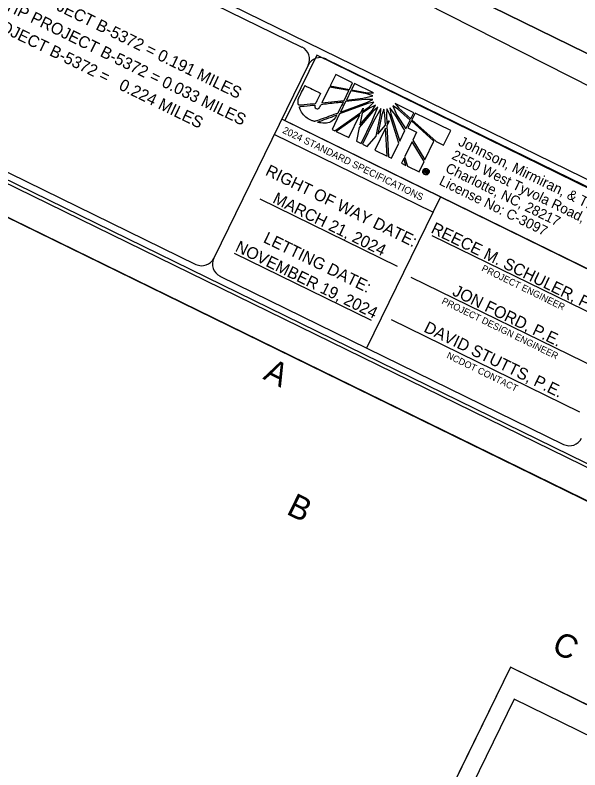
# Model space of a CAD drawing. Extents: x 1517888 to 1526099, y 633375 to 640181.
# Drawn here: x 1519355 to 1520197, y 636669 to 637793 of the extents above; entities that cross this region are included whole.
import ezdxf

# ---------------------------------------------------------------- set-up
doc = ezdxf.new("R2010")
doc.units = 0
for name, color, linetype in [('Scratch_Level_0', 7, 'Continuous'), ('Sheet Clip Boundary CELL', 7, 'Continuous'), ('Sheet Cutting Line CELL', 7, 'Continuous'), ('Sheet Data Field CELL', 7, 'Continuous'), ('Sheet Data Text CELL', 7, 'Continuous'), ('Sheet Plot Border Inside CELL', 7, 'Continuous'), ('Sheet Plot Border Outside CELL', 7, 'Continuous'), ('Sheet Title CELL', 7, 'Continuous')]:
    doc.layers.add(name, color=color, linetype=linetype)

msp = doc.modelspace()

# ---------------------------------------------------------------- linework, layer by layer
at = {"layer": 'Scratch_Level_0'}
msp.add_lwpolyline([(1519830.7, 639089.6), (1521178.1, 638430.5), (1520716.8, 637487.3), (1519369.3, 638146.3)], close=True, dxfattribs=at)
at = {"layer": 'Sheet Clip Boundary CELL'}
msp.add_lwpolyline([(1519997.2, 638878.2), (1520677.9, 638519.7), (1521000.4, 638385.3), (1521102.7, 638308.6), (1521171, 638278.9), (1521396, 638166), (1521492.2, 638121.5), (1521760.4, 637993.1), (1521455.7, 637316.3), (1521359.7, 637143.3), (1520290, 637647.3), (1519534.4, 638030.1)], close=True, dxfattribs=at)
at = {"layer": 'Sheet Cutting Line CELL'}
for p, q in [((1518399.9, 637954.2), (1521425.5, 636474.5)), ((1520093.5, 636822.1), (1519131.3, 634854.8)), ((1523118.1, 635342.8), (1520093.5, 636822.1))]:
    msp.add_line(p, q, dxfattribs=at)
at = {"layer": 'Sheet Plot Border Inside CELL'}
for points in [[(1517931.1, 638233.4), (1520925.2, 636769.1), (1521852.3, 638664.7), (1518858.2, 640129.1)], [(1519172.2, 634879.3), (1522165.4, 633415.4), (1523092.5, 635310.8), (1520099.3, 636774.7)]]:
    msp.add_lwpolyline(points, close=True, dxfattribs=at)
at = {"layer": 'Sheet Plot Border Outside CELL'}
for points in [[(1521880.1, 638701.1), (1518854.6, 640180.8), (1517888, 638204.5), (1520913.6, 636724.8)], [(1519131.3, 634854.8), (1522155.9, 633375.5), (1523118.1, 635342.8), (1520093.5, 636822.1)]]:
    msp.add_lwpolyline(points, close=True, dxfattribs=at)
at = {"layer": 'Sheet Title CELL'}
for p, q in [((1518493.8, 638387), (1521045, 637139.2)), ((1519100.2, 638079.2), (1519782.9, 637745.3)), ((1519818.9, 637727.7), (1520330.9, 637477.3)), ((1519792.1, 637718.6), (1519651.5, 637431.1)), ((1519833.1, 637704.6), (1519824.9, 637687.9)), ((1519858.3, 637692.3), (1519833.1, 637704.6)), ((1519824.9, 637687.9), (1519853.6, 637682.6)), ((1519853.6, 637682.6), (1519858.3, 637692.3)), ((1519861, 637691.2), (1519856.6, 637682.1)), ((1519889.4, 637677.3), (1519861, 637691.2)), ((1519824, 637686), (1519812.5, 637662.5)), ((1519852.7, 637680.7), (1519824, 637686)), ((1519845.6, 637666.1), (1519852.7, 637680.7)), ((1519855.7, 637680.2), (1519849, 637666.5)), ((1519879.7, 637675.7), (1519855.7, 637680.2)), ((1519856.6, 637682.1), (1519880.6, 637677.6)), ((1519880.6, 637677.6), (1519889.4, 637677.3)), ((1519812.5, 637662.5), (1519845.6, 637666.1)), ((1519876.6, 637667.6), (1519847.9, 637664.3)), ((1519849, 637666.5), (1519873.8, 637669.3)), ((1519873.8, 637669.3), (1519888.4, 637672.7)), ((1519888.6, 637667.7), (1519876.6, 637667.6)), ((1519888.4, 637672.7), (1519879.7, 637675.7)), ((1519880.4, 637663.3), (1519888.6, 637667.7)), ((1519880.8, 637661.4), (1519838.9, 637645.9)), ((1519847.9, 637664.3), (1519840.2, 637648.6)), ((1519840.2, 637648.6), (1519880.4, 637663.3)), ((1519870.7, 637648.2), (1519874, 637654.8)), ((1519884.4, 637655.3), (1519872.5, 637646.9)), ((1519873, 637649.6), (1519883, 637656.7)), ((1519874, 637654.8), (1519873, 637649.6)), ((1519890, 637663.3), (1519880.8, 637661.4)), ((1519883, 637656.7), (1519890, 637663.3)), ((1519892.5, 637659.2), (1519884.4, 637655.3)), ((1519887.5, 637635.7), (1519896.1, 637656.1)), ((1519888, 637651.8), (1519892.5, 637659.2)), ((1519896.1, 637656.1), (1519888.7, 637649.7)), ((1519914, 637655.3), (1519915.5, 637646)), ((1519921.4, 637645.7), (1519914, 637655.3)), ((1519918.1, 637658.2), (1519924.5, 637644.3)), ((1519925.4, 637653.4), (1519918.1, 637658.2)), ((1519949.5, 637647.8), (1519921.6, 637661.6)), ((1519921.6, 637661.6), (1519927, 637654.8)), ((1519927, 637654.8), (1519945.1, 637638.8)), ((1519838.9, 637645.9), (1519827.8, 637623)), ((1519831.9, 637621), (1519870.7, 637648.2)), ((1519869, 637644.6), (1519833.9, 637620)), ((1519852.7, 637610.8), (1519869, 637644.6)), ((1519888.7, 637649.7), (1519868.3, 637625.9)), ((1519869.2, 637629.8), (1519888, 637651.8)), ((1519872.5, 637646.9), (1519869.2, 637629.8)), ((1519900.3, 637654.1), (1519889.3, 637634.8)), ((1519893.4, 637613.1), (1519899.7, 637644.4)), ((1519901.8, 637644.7), (1519895.9, 637616)), ((1519899.7, 637644.4), (1519900.3, 637654.1)), ((1519904.9, 637653.2), (1519901.8, 637644.7)), ((1519906.6, 637644.4), (1519904.9, 637653.2)), ((1519907.4, 637629.4), (1519906.6, 637644.4)), ((1519909.6, 637653.7), (1519908.7, 637644.1)), ((1519908.7, 637644.1), (1519909.2, 637631.5)), ((1519913.8, 637645.3), (1519909.6, 637653.7)), ((1519927.2, 637602.5), (1519913.8, 637645.3)), ((1519915.5, 637646), (1519928.5, 637605.2)), ((1519936.4, 637621.3), (1519921.4, 637645.7)), ((1519924.5, 637644.3), (1519937.5, 637623.6)), ((1519944.1, 637636.8), (1519925.4, 637653.4)), ((1519945.1, 637638.8), (1519949.5, 637647.8)), ((1519951.5, 637647), (1519946.8, 637637.3)), ((1520004.6, 637621.1), (1519951.5, 637647)), ((1520300.8, 637370.1), (1519752.8, 637638.2)), ((1519871.1, 637602), (1519887.5, 637635.7)), ((1519889.3, 637634.8), (1519872.9, 637601.1)), ((1519909.2, 637631.5), (1519913, 637635.8)), ((1519913, 637635.8), (1519909.4, 637628.4)), ((1519937.5, 637623.6), (1519944.1, 637636.8)), ((1519945.8, 637635.3), (1519940.9, 637625.1)), ((1519945.9, 637635.5), (1519945.8, 637635.3)), ((1519979.6, 637605.2), (1519945.9, 637635.5)), ((1519946.8, 637637.3), (1519946.6, 637637)), ((1519946.6, 637637), (1519982.7, 637604.9)), ((1519827.8, 637623), (1519831.9, 637621)), ((1519868.3, 637625.9), (1519864.2, 637605.4)), ((1519907.6, 637624.8), (1519891.6, 637592)), ((1519895.9, 637616), (1519907.4, 637629.4)), ((1519909.7, 637583.2), (1519907.6, 637624.8)), ((1519909.4, 637628.4), (1519911.7, 637582)), ((1519928.5, 637605.2), (1519936.4, 637621.3)), ((1519940.9, 637625.1), (1519953.8, 637618.8)), ((1519994, 637599.4), (1520004.6, 637621.1)), ((1519977.9, 637499.6), (1519741.6, 637615.3)), ((1519833.9, 637620), (1519852.7, 637610.8)), ((1519879.9, 637597.7), (1519893.4, 637613.1)), ((1519953.8, 637618.8), (1519947.9, 637606.7)), ((1519864.2, 637605.4), (1519871.1, 637602)), ((1519872.9, 637601.1), (1519879.9, 637597.7)), ((1519916.1, 637579.9), (1519927.2, 637602.5)), ((1519946.9, 637604.6), (1519935.9, 637582.1)), ((1519965, 637575.4), (1519946.9, 637604.6)), ((1519947.9, 637606.7), (1519966, 637577.4)), ((1519966, 637577.4), (1519979.6, 637605.2)), ((1519982.7, 637604.9), (1519994, 637599.4)), ((1519891.6, 637592), (1519909.7, 637583.2)), ((1519911.7, 637582), (1519916.1, 637579.9)), ((1519934.7, 637579.6), (1519931.2, 637572.5)), ((1519937.8, 637569.3), (1519934.7, 637579.6)), ((1519935.9, 637582.1), (1519940.3, 637568.1)), ((1519931.2, 637572.5), (1519937.8, 637569.3)), ((1519940.3, 637568.1), (1519957.4, 637559.8)), ((1519957.4, 637559.8), (1519965, 637575.4)), ((1519969.8, 637564.3), (1519969.4, 637563.5)), ((1519969.4, 637563.5), (1519969.8, 637564.3)), ((1519965.2, 637558.9), (1519967.1, 637562.8)), ((1519966.1, 637558.5), (1519965.2, 637558.9)), ((1519966, 637556.6), (1519965.6, 637555.8)), ((1519965.6, 637555.8), (1519966, 637556.6)), ((1519965.7, 637555.8), (1519965.6, 637555.8)), ((1519966, 637556.6), (1519966.1, 637556.6)), ((1519966.8, 637560), (1519966.1, 637558.5)), ((1519967.5, 637559.6), (1519966.8, 637560)), ((1519967.1, 637562.8), (1519968.6, 637562)), ((1519967.6, 637561.6), (1519967.1, 637560.7)), ((1519967.1, 637560.7), (1519967.8, 637560.3)), ((1519967.8, 637560.3), (1519967.5, 637559.6)), ((1519967.5, 637559.6), (1519967.8, 637560.3)), ((1519967.5, 637559.6), (1519967.5, 637559.6)), ((1519968.3, 637561.2), (1519967.6, 637561.6)), ((1519967.8, 637560.3), (1519967.9, 637560.3)), ((1519968.6, 637562), (1519968.3, 637561.2)), ((1519968.3, 637561.2), (1519968.6, 637562)), ((1519968.4, 637561.2), (1519968.3, 637561.2)), ((1519968.6, 637562), (1519968.9, 637561.9)), ((1519909.9, 637533), (1519909.9, 637533)), ((1519989.2, 637522.6), (1519879.1, 637297.5)), ((1519925.1, 637419), (1519720.8, 637518.9)), ((1519822.9, 637468.9), (1519822.9, 637468.9)), ((1519976.5, 637465.2), (1520255.2, 637328.9)), ((1519886.7, 637338.5), (1519682.3, 637438.4)), ((1519945.3, 637403), (1520226, 637265.7)), ((1519916, 637339.8), (1520196.7, 637202.5))]:
    msp.add_line(p, q, dxfattribs=at)
for points in [[(1519396, 638200.8), (1519369.3, 638146.3), (1520716.8, 637487.3)], [(1518228, 638093.9), (1520887, 636793.4)], [(1518942.1, 637755.8), (1519624.8, 637421.9)], [(1519824.9, 637687.9), (1519853.6, 637682.6), (1519858.3, 637692.3), (1519833.1, 637704.6), (1519824.9, 637687.9)], [(1519880.6, 637677.6), (1519889.4, 637677.3), (1519861, 637691.2), (1519856.6, 637682.1), (1519880.6, 637677.6)], [(1519812.5, 637662.5), (1519845.6, 637666.1), (1519852.7, 637680.7), (1519824, 637686), (1519812.5, 637662.5)], [(1519855.7, 637680.2), (1519849, 637666.5), (1519873.8, 637669.3), (1519888.4, 637672.7), (1519879.7, 637675.7), (1519855.7, 637680.2)], [(1519847.9, 637664.3), (1519840.2, 637648.6), (1519880.4, 637663.3), (1519888.6, 637667.7), (1519876.6, 637667.6), (1519847.9, 637664.3)], [(1519890, 637663.3), (1519880.8, 637661.4), (1519838.9, 637645.9), (1519827.8, 637623), (1519831.9, 637621), (1519870.7, 637648.2), (1519874, 637654.8), (1519873, 637649.6), (1519883, 637656.7), (1519890, 637663.3)], [(1519888.7, 637649.7), (1519868.3, 637625.9), (1519864.2, 637605.4), (1519871.1, 637602), (1519887.5, 637635.7), (1519896.1, 637656.1), (1519888.7, 637649.7)], [(1519892.5, 637659.2), (1519884.4, 637655.3), (1519872.5, 637646.9), (1519869.2, 637629.8), (1519888, 637651.8), (1519892.5, 637659.2)], [(1519914, 637655.3), (1519915.5, 637646), (1519928.5, 637605.2), (1519936.4, 637621.3), (1519921.4, 637645.7), (1519914, 637655.3)], [(1519918.1, 637658.2), (1519924.5, 637644.3), (1519937.5, 637623.6), (1519944.1, 637636.8), (1519925.4, 637653.4), (1519918.1, 637658.2)], [(1519927, 637654.8), (1519945.1, 637638.8), (1519949.5, 637647.8), (1519921.6, 637661.6), (1519927, 637654.8)], [(1519833.9, 637620), (1519852.7, 637610.8), (1519869, 637644.6), (1519833.9, 637620)], [(1519900.3, 637654.1), (1519889.3, 637634.8), (1519872.9, 637601.1), (1519879.9, 637597.7), (1519893.4, 637613.1), (1519899.7, 637644.4), (1519900.3, 637654.1)], [(1519904.9, 637653.2), (1519901.8, 637644.7), (1519895.9, 637616), (1519907.4, 637629.4), (1519906.6, 637644.4), (1519904.9, 637653.2)], [(1519909.6, 637653.7), (1519908.7, 637644.1), (1519909.2, 637631.5), (1519913, 637635.8), (1519909.4, 637628.4), (1519911.7, 637582), (1519916.1, 637579.9), (1519927.2, 637602.5), (1519913.8, 637645.3), (1519909.6, 637653.7)], [(1520004.6, 637621.1), (1519951.5, 637647), (1519946.8, 637637.3), (1519946.6, 637637), (1519982.7, 637604.9), (1519994, 637599.4), (1520004.6, 637621.1)], [(1519945.9, 637635.5), (1519945.8, 637635.3), (1519940.9, 637625.1), (1519953.8, 637618.8), (1519947.9, 637606.7), (1519966, 637577.4), (1519979.6, 637605.2), (1519945.9, 637635.5)], [(1519891.6, 637592), (1519909.7, 637583.2), (1519907.6, 637624.8), (1519891.6, 637592)], [(1519946.9, 637604.6), (1519935.9, 637582.1), (1519940.3, 637568.1), (1519957.4, 637559.8), (1519965, 637575.4), (1519946.9, 637604.6), (1519946.9, 637604.6)], [(1519931.2, 637572.5), (1519931.2, 637572.5), (1519937.8, 637569.3), (1519934.7, 637579.6), (1519931.2, 637572.5)], [(1519968.9, 637558.2), (1519968.8, 637558), (1519968.8, 637557.8), (1519968.7, 637557.7), (1519968.6, 637557.2), (1519967.8, 637557.6)], [(1519660.7, 637404.4), (1520172.7, 637153.9)]]:
    msp.add_lwpolyline(points, dxfattribs=at)
msp.add_lwpolyline([(1519757.2, 637636), (1520296.3, 637372.3), (1520343.9, 637469.6), (1519804.8, 637733.3)], close=True, dxfattribs=at)
for centre, start, end in [((1519774.2, 637727.4), 333.9377, 63.9377), ((1519810.1, 637709.9), 63.9377, 153.9377), ((1519633.6, 637440), 243.9377, 333.9377), ((1519669.5, 637422.4), 153.9377, 243.9377), ((1520181.6, 637172), 243.9377, 333.9377)]:
    msp.add_arc(centre, 20, start, end, dxfattribs=at)
for points, degree in [([(1519810.6, 637676.8), (1519810.6, 637676.8), (1519787.2, 637688.2), (1519787.2, 637688.2), (1519787.2, 637688.2), (1519780.1, 637673.6), (1519780.1, 637673.6), (1519780.1, 637673.6), (1519779.3, 637672.1), (1519779.3, 637672.1), (1519777.1, 637667.5), (1519776.8, 637663.1), (1519778, 637658.8), (1519778, 637658.8), (1519802.9, 637661.1), (1519803, 637661.4), (1519803, 637661.4), (1519810.6, 637676.8), (1519810.6, 637676.8)], 3), ([(1519803.9, 637654), (1519802.4, 637654.7), (1519801.5, 637656.2), (1519802.4, 637659.3), (1519802.4, 637659.3), (1519778.8, 637656.9), (1519778.8, 637656.9), (1519781.5, 637648.3), (1519788.7, 637640.5), (1519796.2, 637636.8), (1519798.2, 637635.8), (1519799.8, 637635.3), (1519802.1, 637634.7), (1519802.1, 637634.7), (1519836.3, 637647.1), (1519836.3, 637647.1), (1519836.3, 637647.1), (1519844.5, 637664), (1519844.5, 637664), (1519844.5, 637664), (1519811.5, 637660.3), (1519811.5, 637660.3), (1519808.4, 637654), (1519806, 637653), (1519803.9, 637654)], 3), ([(1519803.9, 637654), (1519802.4, 637654.7), (1519801.5, 637656.2), (1519802.4, 637659.3), (1519802.4, 637659.3), (1519778.8, 637656.9), (1519778.8, 637656.9), (1519781.5, 637648.3), (1519788.7, 637640.5), (1519796.2, 637636.8), (1519798.2, 637635.8), (1519799.8, 637635.3), (1519802.1, 637634.7), (1519802.1, 637634.7), (1519836.3, 637647.1), (1519836.3, 637647.1), (1519836.3, 637647.1), (1519844.5, 637664), (1519844.5, 637664), (1519844.5, 637664), (1519811.5, 637660.3), (1519811.5, 637660.3), (1519808.4, 637654), (1519806, 637653), (1519803.9, 637654)], 3), ([(1519835, 637644.4), (1519835, 637644.4), (1519805.4, 637633.7), (1519805.4, 637633.7), (1519816.2, 637631.4), (1519828.9, 637633.1), (1519835, 637644.4)], 3), ([(1519965.6, 637555.8), (1519964.5, 637556.3), (1519963.6, 637557.3), (1519963.2, 637558.5), (1519962.8, 637559.7), (1519962.8, 637560.9), (1519963.4, 637562.1), (1519964, 637563.3), (1519964.9, 637564.1), (1519966.1, 637564.5), (1519967.4, 637564.9), (1519968.6, 637564.8), (1519969.8, 637564.3)], 3), ([(1519969.8, 637564.3), (1519971, 637563.7), (1519971.8, 637562.8), (1519972.2, 637561.5), (1519972.7, 637560.4), (1519972.6, 637559.1), (1519972, 637557.9)], 3), ([(1519969.4, 637563.5), (1519968.4, 637563.9), (1519967.5, 637564), (1519966.5, 637563.7), (1519965.5, 637563.3), (1519964.7, 637562.7), (1519964.3, 637561.7), (1519963.8, 637560.8), (1519963.7, 637559.8), (1519964.1, 637558.8), (1519964.4, 637557.8), (1519965.1, 637557.1), (1519966, 637556.6)], 3), ([(1519972, 637557.9), (1519971.4, 637556.8), (1519970.5, 637555.9), (1519969.3, 637555.5), (1519968.1, 637555.1), (1519966.8, 637555.2), (1519965.7, 637555.8)], 3), ([(1519966.1, 637556.6), (1519967, 637556.1), (1519968, 637556.1), (1519969, 637556.4), (1519970, 637556.7), (1519970.7, 637557.4), (1519971.2, 637558.4), (1519971.6, 637559.3), (1519971.7, 637560.3), (1519971.4, 637561.3), (1519971, 637562.3), (1519970.3, 637563), (1519969.4, 637563.5)], 3), ([(1519968.1, 637559.1), (1519968.1, 637559.3), (1519967.9, 637559.4), (1519967.5, 637559.6)], 2), ([(1519967.8, 637557.6), (1519967.8, 637557.9), (1519967.8, 637558.1), (1519967.9, 637558.4), (1519968.1, 637558.8), (1519968.2, 637559), (1519968.1, 637559.1)], 3), ([(1519967.9, 637560.3), (1519968.4, 637560), (1519968.8, 637560.1), (1519969, 637560.4), (1519969.1, 637560.7), (1519968.9, 637560.9), (1519968.4, 637561.2)], 3), ([(1519968.9, 637561.9), (1519969.9, 637561.4), (1519970.2, 637560.8), (1519969.8, 637560), (1519969.6, 637559.6), (1519969.4, 637559.4), (1519968.9, 637559.4)], 3), ([(1519968.9, 637559.4), (1519969.1, 637559.1), (1519969.1, 637558.7), (1519968.9, 637558.2)], 2)]:
    msp.add_open_spline(points, degree=degree, dxfattribs=at)

# ---------------------------------------------------------------- texts
at = {"layer": 'Sheet Data Field CELL'}
for s, height, p in [('LENGTH OF ROADWAY TIP PROJECT B-5372 = 0.191 MILES', 17.5, (1519091.2, 637959.7)), ('LENGTH OF STRUCTURE TIP PROJECT B-5372 = 0.033 MILES', 17.5, (1519076.6, 637930.1)), ('TOTAL LENGTH OF TIP PROJECT B-5372 =   0.224 MILES', 17.5, (1519063, 637901.2)), ('MARCH 21, 2024', 17.509, (1519737.9, 637514.4)), ('REECE M. SCHULER, P.E, P.L.S', 17.5, (1519973.8, 637469.8)), ('NOVEMBER 19, 2024', 17.509, (1519682.1, 637442.4)), ('JON FORD, P.E.', 17.5, (1520005.7, 637376.7)), ('DAVID STUTTS, P.E.', 17.5, (1519963.2, 637322.4)), ('A', 35, (1519723.5, 637251.9)), ('B', 35, (1519758.2, 637051)), ('C', 35, (1520153.3, 636845.9))]:
    msp.add_text(s, height=height, rotation=333.9377, dxfattribs=at).set_placement(p)
at = {"layer": 'Sheet Data Text CELL'}
msp.add_text('1A                      INDEX OF SHEETS, GENERAL NOTES, AND STANDARD DRAWINGS', height=8, rotation=333.9377, dxfattribs=at).set_placement((1519152.9, 636721.7))
at = {"layer": 'Sheet Title CELL'}
for s, height, p in [('2024 STANDARD SPECIFICATIONS', 10.4, (1519753, 637618.2)), ('Johnson, Mirmiran, & Thompson Inc.', 15.334, (1520014.6, 637599.8)), ('2550 West Tyvola Road, Suite 120,', 14.895, (1520004.8, 637579.6)), ('RIGHT OF WAY DATE: ', 17.5, (1519727.1, 637555.7)), ('Charlotte, NC, 28217', 14.895, (1519995.4, 637560.4)), ('License No: C-3097', 14.895, (1519986.1, 637541.3)), ('LETTING DATE:', 17.5, (1519724, 637455.5)), ('PROJECT ENGINEER', 9.999, (1520049.6, 637412.8)), ('PROJECT DESIGN ENGINEER', 9.999, (1519990.2, 637364.2)), ('NCDOT CONTACT', 9.999, (1519997.5, 637283.1))]:
    msp.add_text(s, height=height, rotation=333.9377, dxfattribs=at).set_placement(p)

doc.saveas('drawing.dxf')
